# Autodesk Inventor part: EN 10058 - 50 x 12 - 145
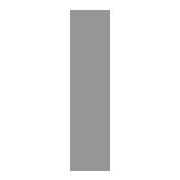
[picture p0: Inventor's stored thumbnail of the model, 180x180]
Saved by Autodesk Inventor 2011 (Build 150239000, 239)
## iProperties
Created: 2010-02
Part Number: EN 10058 - 50 x 12 - 145
Material: Steel, Mild
Description: flat steel bar 50*12
Document SubType Name: Modeling
Standard: DIN
Designer: PC
Standard Revision: 2004
Standards Organization: DIN
Language: en-US
Size Designation: 50 x 12
Categories: <MemberInstance><Categories><Category DisplayName="Structural Shapes" InternalName="089c4875-fa83-4c05-b084-43b9cc11f5ed" Mnemonic="GRDR"><CategoryParameter Dis
Stock Number: 50 x 12
Density: 7.86 g/cm^3
G_L: 145.000 mm
G_W: 12.000 mm
G_H: 50.000 mm
IsCustomPart: 1
Author: PC
_CCFamilyMember: 60
_CCFamilyDisplayName: DIN EN 10058 - Hot rolled flat steel bars for general purposes
_FrameMemberDoc: Frame Member File
_Version: 15.0.0
_GetPNFromCC: 1
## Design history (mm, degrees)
node "Start plane"
node "End plane"
sketch "Sketch"
  geometry: L1 (6, -25)-(-6, -25); L2 (-6, -25)-(-6, 25); L3 (-6, 25)-(6, 25); L4 (6, 25)-(6, -25); L5 (-6, 0)-(8, 0); L6 (0, -30)-(0, 40); L7 (0, 54)-(0, -44) reference; L8 (-9.2, 0)-(13.2, 0) reference
  constraints: 12 end point, 2 collinear, 2 parallel, 1 horizontal, 1 perpendicular
  dimensions: "d0" = 50 distance between parallel lines of L3 L1 (= G_W); "d1" = 12 distance between parallel lines of L4 L2 (= G_H); "d4" = 6 distance between parallel lines of L6 L4 (= 0.5 x d1); "d5" = 25 distance between parallel lines of L5 L3 (= 0.5 x d0)
extrude "Body" new body sketch "Sketch" stored distance "d2" = 145 (= G_L); taper "d3" = 0 deg
node "Driven Length"
  sketch "Sketch3"
    geometry: L1 (0, 0)-(10, 0) reference
    constraints: 2 end point, 1 horizontal
  workplane "Work Plane3"
  sketch "Sketch4"
    geometry: L1 (-2, 0)-(12, 0) reference; L2 (-2, 145)-(12, 145) reference
    dimensions: "d9" = 145 distance between parallel lines of L1 L2 (derived)
body "Solid1"
other parameters: "G_W" = 50 [user parameter; used in 1 equation term], "G_H" = 12 [user parameter; used in 1 equation term], "G_L" = 145 (= d9) [user parameter; used in 1 equation term], "G_OFFSET_START" = 0 [user parameter; used in 1 equation term], "G_OFFSET_END" = 0 [user parameter; used in 1 equation term], "d6" = 0 (computed from G_OFFSET_START), "d7" = 145 (= G_OFFSET_END + B_L), "B_L" = 145 [user parameter; used in 1 equation term], "d8" = 90 deg, "MAS" = 0.471 [user parameter]
